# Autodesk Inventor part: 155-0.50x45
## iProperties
Created: 2007-06
Part Number: 155-0.50x45
Document SubType Name: Modeling
Designer: btaylor
Density: 1 g/cm^3
Author: btaylor
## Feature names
1. Sweep1
2. Extrusion1
3. Extrusion2
4. Fillet1
5. Fillet2
6. Extrusion3
7. Extrusion4
8. Sweep2
9. Fillet3
10. Fillet4
11. Chamfer1
12. Chamfer2
13. Fillet5
14. Fillet6
